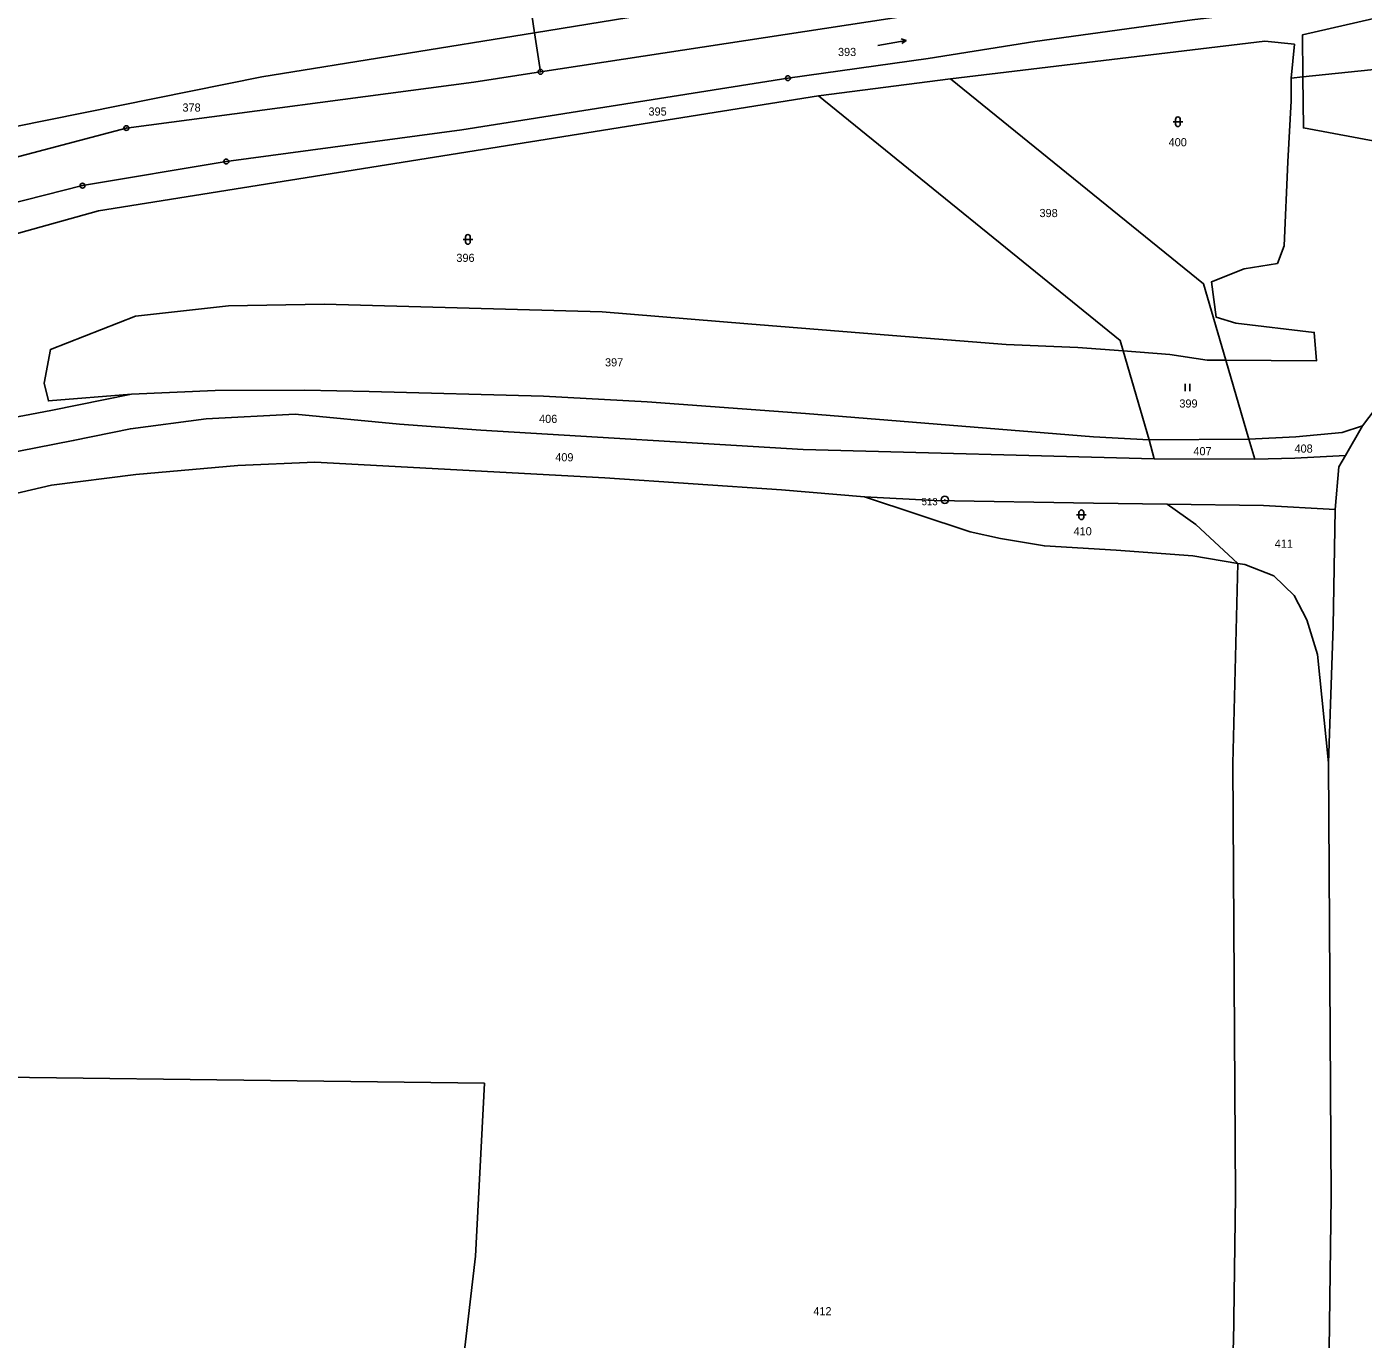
# Model space of a CAD drawing. Extents: x -769392 to -767038, y -1018329 to -1015269.
# Drawn here: x -768805 to -768526.3, y -1016709.8 to -1016436.2 of the extents above; entities that cross this region are included whole.
import ezdxf
from ezdxf.enums import TextEntityAlignment as Align

# ---------------------------------------------------------------- set-up
doc = ezdxf.new("R2010")
doc.units = 0
doc.header["$LTSCALE"] = 0.68
for name, color, linetype, lineweight in [('1', 7, 'Continuous', 25), ('3', 7, 'Continuous', 25), ('8', 7, 'Continuous', 25)]:
    doc.layers.add(name, color=color, linetype=linetype, lineweight=lineweight)
doc.layers.add('2', color=7, linetype='Continuous')

msp = doc.modelspace()

# ---------------------------------------------------------------- linework, layer by layer
at = {"layer": '1'}
for p, q in [((-768699.1, -1016437.44), (-768712.03, -1016352.77)), ((-768657.6, -1016430.72), (-768699.1, -1016437.44)), ((-768697.86, -1016445.59), (-768699.1, -1016437.44)), ((-768466.24, -1016439.01), (-768538.91, -1016446.63)), ((-768612.4, -1016447.08), (-768639.88, -1016450.6)), ((-768538.91, -1016446.63), (-768541.33, -1016446.88)), ((-768576.36, -1016503.77), (-768570.94, -1016522.28)), ((-768554.95, -1016505.7), (-768550.13, -1016522.18)), ((-768530.02, -1016525.56), (-768526.45, -1016519.39)), ((-768570.94, -1016522.28), (-768550.13, -1016522.18)), ((-768570.94, -1016522.28), (-768569.89, -1016526.24)), ((-768550.13, -1016522.18), (-768548.93, -1016526.32)), ((-768548.93, -1016526.32), (-768569.89, -1016526.24))]:
    msp.add_line(p, q, dxfattribs=at)
for points in [[(-768845.93, -1016484.91), (-768809.19, -1016473.29), (-768793.36, -1016469.31), (-768763.37, -1016464.27), (-768714.25, -1016457.68), (-768646.26, -1016446.91), (-768617.02, -1016442.83), (-768594.78, -1016439.25), (-768561.97, -1016434.72), (-768507.31, -1016428.23), (-768491.93, -1016427.01)], [(-768491.93, -1016427.01), (-768538.99, -1016437.9), (-768538.91, -1016446.63)], [(-768697.86, -1016445.59), (-768599.92, -1016430.64), (-768597.61, -1016430.31)], [(-768699.1, -1016437.44), (-768755.97, -1016446.64), (-768852.11, -1016465.98)], [(-768541.33, -1016446.88), (-768540.66, -1016439.84), (-768546.85, -1016439.22), (-768612.4, -1016447.08)], [(-768848.61, -1016476.7), (-768835.52, -1016471.56), (-768817.2, -1016466), (-768784.22, -1016457.31), (-768711.78, -1016447.71), (-768697.86, -1016445.59)], [(-768612.4, -1016447.08), (-768559.63, -1016489.74), (-768554.95, -1016505.7)], [(-768554.95, -1016505.7), (-768536.06, -1016505.84), (-768536.53, -1016499.91), (-768552.86, -1016497.94), (-768556.99, -1016496.71), (-768557.96, -1016489.39), (-768551.15, -1016486.67), (-768544.19, -1016485.53), (-768542.79, -1016481.87), (-768542.06, -1016464.38), (-768541.31, -1016451.64), (-768541.33, -1016446.88)], [(-768538.91, -1016446.63), (-768538.8, -1016457.27), (-768495.96, -1016465.27)], [(-768639.88, -1016450.6), (-768790.05, -1016474.53), (-768845.61, -1016490.04)], [(-768576.36, -1016503.77), (-768577.01, -1016501.56), (-768639.88, -1016450.6)], [(-768486.38, -1016466.97), (-768490.45, -1016472.45), (-768499.34, -1016483.75), (-768526.45, -1016519.39)], [(-768783.11, -1016512.74), (-768800.45, -1016514.19), (-768801.35, -1016510.45), (-768800.03, -1016503.46), (-768782.32, -1016496.54), (-768762.88, -1016494.34), (-768742.97, -1016493.99), (-768684.99, -1016495.58), (-768654.61, -1016498.11), (-768624.44, -1016500.56), (-768600.73, -1016502.39), (-768585.8, -1016503.07), (-768576.36, -1016503.77)], [(-768576.36, -1016503.77), (-768566.65, -1016504.48), (-768558.87, -1016505.67), (-768554.95, -1016505.7)], [(-768783.11, -1016512.74), (-768799.97, -1016516.17), (-768816.48, -1016519.29), (-768833.89, -1016523.08), (-768853.5, -1016522.25)], [(-768783.11, -1016512.74), (-768765.7, -1016511.99), (-768747.04, -1016511.94), (-768733.56, -1016512.21), (-768697.25, -1016513.2), (-768675.59, -1016514.37), (-768642.6, -1016516.77), (-768582.53, -1016521.69), (-768570.94, -1016522.28)], [(-768569.89, -1016526.24), (-768643.08, -1016524.32), (-768710.32, -1016520.28), (-768727.29, -1016519.02), (-768749.01, -1016516.91), (-768767.55, -1016517.9), (-768783.35, -1016519.98), (-768795.27, -1016522.46), (-768810.52, -1016525.38), (-768825.15, -1016530.96), (-768847.91, -1016545.05)], [(-768526.45, -1016519.39), (-768530.69, -1016520.74), (-768540.39, -1016521.64), (-768550.13, -1016522.18)], [(-768848.46, -1016562.3), (-768840.1, -1016554.46), (-768830.33, -1016544.64), (-768821.12, -1016538.96), (-768810.22, -1016534.2), (-768799.81, -1016531.76), (-768782.22, -1016529.49), (-768760.96, -1016527.63), (-768744.94, -1016526.96), (-768684.45, -1016530.22), (-768647.61, -1016532.74), (-768630.31, -1016534.17)], [(-768530.02, -1016525.56), (-768540.54, -1016526.11), (-768548.93, -1016526.32)], [(-768532.13, -1016536.8), (-768531.37, -1016527.89), (-768530.02, -1016525.56)], [(-768630.31, -1016534.17), (-768608.25, -1016541.43), (-768601.92, -1016542.84), (-768592.79, -1016544.39), (-768577.8, -1016545.29), (-768561.81, -1016546.47), (-768552.43, -1016548.05)], [(-768630.31, -1016534.17), (-768615.71, -1016534.96), (-768582.52, -1016535.52), (-768567.18, -1016535.72)], [(-768567.18, -1016535.72), (-768547.13, -1016535.98), (-768532.13, -1016536.8)], [(-768552.43, -1016548.05), (-768561.23, -1016539.96), (-768567.18, -1016535.72)], [(-768533.52, -1016589.6), (-768532.6, -1016561.11), (-768532.13, -1016536.8)], [(-768587.55, -1016903.34), (-768583.51, -1016882.65), (-768573.27, -1016833.05), (-768558.06, -1016752.58), (-768553.38, -1016710.65), (-768552.97, -1016679.91), (-768553.52, -1016589.72), (-768552.43, -1016548.05)], [(-768552.43, -1016548.05), (-768551.03, -1016548.29), (-768544.96, -1016550.6), (-768540.74, -1016554.74), (-768538.08, -1016559.81), (-768535.84, -1016567.01), (-768533.52, -1016589.6)], [(-768848.46, -1016562.3), (-768853.92, -1016586.39), (-768852.75, -1016627.45), (-768857.98, -1016646.9), (-768854.66, -1016654.57), (-768709.56, -1016656.38), (-768711.43, -1016692.43), (-768726.18, -1016819.2), (-768799.78, -1016810.61), (-768863.57, -1016806.4), (-768872.45, -1016870.09)], [(-768567.75, -1016905.65), (-768566.14, -1016897.06), (-768553.66, -1016836.94), (-768538.27, -1016755.55), (-768533.4, -1016711.9), (-768532.97, -1016679.98), (-768533.52, -1016589.6)]]:
    msp.add_lwpolyline(points, dxfattribs=at)
at = {"layer": '3'}
for p, q in [((-768621.627, -1016439.025), (-768622.502, -1016439.688)), ((-768565.951, -1016455.991), (-768563.949, -1016455.991)), ((-768565.451, -1016455.491), (-768565.451, -1016456.492)), ((-768564.449, -1016456.492), (-768564.449, -1016455.491)), ((-768714.001, -1016480.511), (-768711.999, -1016480.511)), ((-768713.501, -1016480.011), (-768713.501, -1016481.012)), ((-768712.499, -1016481.012), (-768712.499, -1016480.011)), ((-768563.461, -1016512.12), (-768563.461, -1016510.62)), ((-768562.46, -1016512.12), (-768562.46, -1016510.62)), ((-768586.081, -1016537.911), (-768584.079, -1016537.911)), ((-768585.581, -1016537.411), (-768585.581, -1016538.412)), ((-768584.579, -1016538.412), (-768584.579, -1016537.411))]:
    msp.add_line(p, q, dxfattribs=at)
msp.add_lwpolyline([(-768627.536, -1016440.066), (-768621.627, -1016439.025), (-768622.677, -1016438.7)], dxfattribs=at)
for centre, start, end in [((-768564.95, -1016455.4909), 0, 180), ((-768564.95, -1016456.4909), 180, 359.98789), ((-768713, -1016480.0109), 0, 180), ((-768713, -1016481.0109), 180, 359.98789), ((-768585.08, -1016537.4109), 0, 180), ((-768585.08, -1016538.4109), 180, 359.98789)]:
    msp.add_arc(centre, 0.5, start, end, dxfattribs=at)
at = {"layer": '8'}
for centre, radius in [((-768697.86, -1016445.5899), 0.5), ((-768697.86, -1016445.5899), 0.0303), ((-768646.26, -1016446.9099), 0.5), ((-768646.26, -1016446.9099), 0.0303), ((-768784.22, -1016457.3099), 0.5), ((-768784.22, -1016457.3099), 0.0303), ((-768763.37, -1016464.2699), 0.5), ((-768763.37, -1016464.2699), 0.0303), ((-768793.36, -1016469.3099), 0.5), ((-768793.36, -1016469.3099), 0.0303), ((-768613.55, -1016534.7998), 0.75), ((-768613.55, -1016534.7998), 0.03)]:
    msp.add_circle(centre, radius, dxfattribs=at)

# ---------------------------------------------------------------- texts
at = {"layer": '2'}
for s, p in [('393', (-768635.83, -1016442.295)), ('378', (-768772.51, -1016453.875)), ('395', (-768675.34, -1016454.705)), ('400', (-768566.89, -1016461.105)), ('398', (-768593.81, -1016475.865)), ('396', (-768715.4, -1016485.205)), ('397', (-768684.41, -1016506.985)), ('399', (-768564.65, -1016515.565)), ('406', (-768698.15, -1016518.765)), ('407', (-768561.72, -1016525.505)), ('408', (-768540.64, -1016524.955)), ('409', (-768694.78, -1016526.765)), ('410', (-768586.71, -1016542.195)), ('411', (-768544.76, -1016544.775)), ('412', (-768640.97, -1016704.755))]:
    msp.add_text(s, height=1.7, dxfattribs=at).set_placement(p)
at = {"layer": '8'}
msp.add_text('513', height=1.5, dxfattribs=at).set_placement((-768615.049, -1016535.917), align=Align.RIGHT)

doc.saveas('drawing.dxf')
